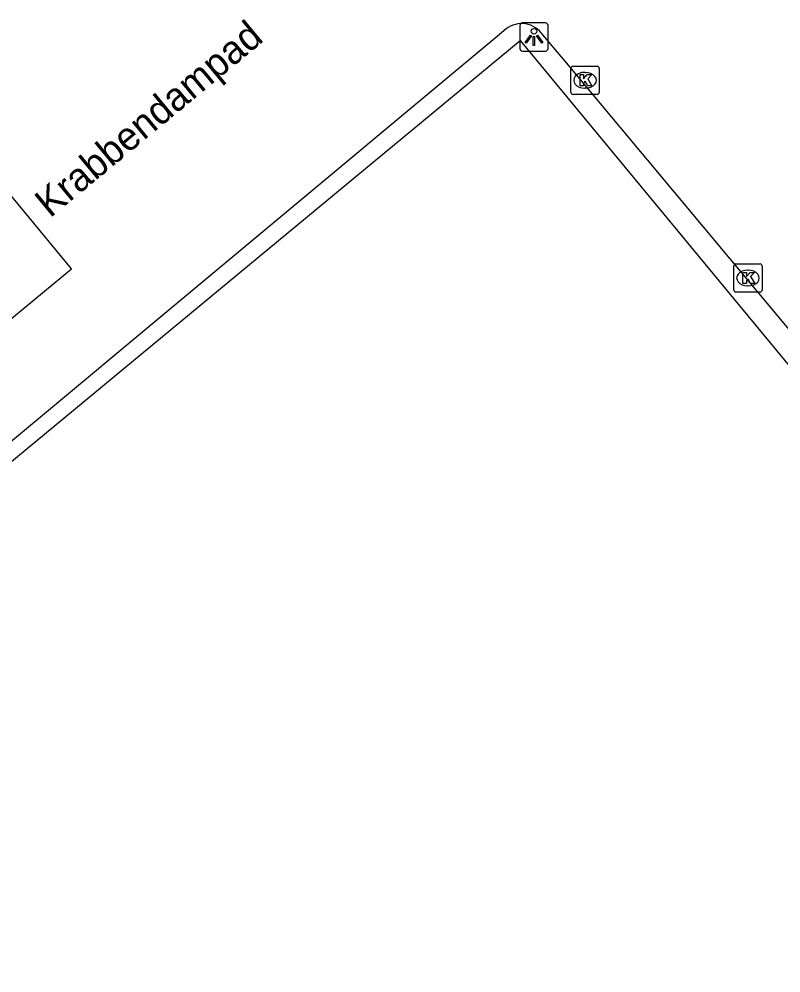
# Model space of a CAD drawing. Extents: x 161087 to 161922, y 382574 to 383873.
# Drawn here: x 161236.47 to 161263.45, y 383205.8 to 383239.57 of the extents above; entities that cross this region are included whole.
import ezdxf

# ---------------------------------------------------------------- set-up
doc = ezdxf.new("R2010")
doc.units = 0
for name, color, linetype in [('IMGEO_Kolk', 7, 'Continuous'), ('IMGEO_Lichtpunt', 7, 'Continuous'), ('IMGEO_Openbare_ruimte_label', 7, 'Continuous'), ('IMGEO_Pand', 7, 'Continuous'), ('IMGEO_Rijbaan_lokaal_open', 7, 'Continuous')]:
    doc.layers.add(name, color=color, linetype=linetype)

msp = doc.modelspace()

# ---------------------------------------------------------------- linework, layer by layer
at = {"layer": 'IMGEO_Kolk'}
for p, q in [((161256.018, 383236.98), (161256.018, 383237.832)), ((161256.093, 383237.906), (161256.945, 383237.906)), ((161256.506, 383237.686), (161256.531, 383237.686)), ((161257.019, 383237.832), (161257.019, 383236.98)), ((161256.529, 383237.126), (161256.504, 383237.126)), ((161256.945, 383236.906), (161256.093, 383236.906)), ((161261.861, 383230.906), (161262.713, 383230.906)), ((161261.786, 383229.98), (161261.786, 383230.832)), ((161262.274, 383230.686), (161262.299, 383230.686)), ((161262.787, 383230.832), (161262.787, 383229.98)), ((161262.713, 383229.906), (161261.861, 383229.906)), ((161262.297, 383230.126), (161262.272, 383230.126))]:
    msp.add_line(p, q, dxfattribs=at)
for points in [[(161256.018, 383236.98), (161256.018, 383237.832)], [(161256.093, 383237.906), (161256.945, 383237.906)], [(161257.019, 383237.832), (161257.019, 383236.98)], [(161256.339, 383237.606), (161256.462, 383237.606), (161256.462, 383237.455), (161256.592, 383237.606), (161256.756, 383237.606), (161256.61, 383237.455), (161256.763, 383237.206), (161256.611, 383237.206), (161256.526, 383237.37), (161256.462, 383237.303), (161256.462, 383237.206), (161256.339, 383237.206), (161256.339, 383237.606)], [(161256.945, 383236.906), (161256.093, 383236.906)], [(161261.861, 383230.906), (161262.713, 383230.906)], [(161261.786, 383229.98), (161261.786, 383230.832)], [(161262.107, 383230.606), (161262.23, 383230.606), (161262.23, 383230.455), (161262.36, 383230.606), (161262.524, 383230.606), (161262.378, 383230.455), (161262.531, 383230.206), (161262.379, 383230.206), (161262.294, 383230.37), (161262.23, 383230.303), (161262.23, 383230.206), (161262.107, 383230.206), (161262.107, 383230.606)], [(161262.787, 383230.832), (161262.787, 383229.98)], [(161262.713, 383229.906), (161261.861, 383229.906)]]:
    msp.add_lwpolyline(points, dxfattribs=at)
for centre, start, end in [((161256.095, 383237.83), 91.552, 178.448), ((161256.095, 383237.83), 91.552, 178.448), ((161256.943, 383237.83), 1.552, 88.448), ((161256.943, 383237.83), 1.552, 88.448), ((161256.095, 383236.982), 181.552, 268.448), ((161256.095, 383236.982), 181.552, 268.448), ((161256.943, 383236.982), 271.552, 358.448), ((161256.943, 383236.982), 271.552, 358.448), ((161261.863, 383230.83), 91.552, 178.448), ((161261.863, 383230.83), 91.552, 178.448), ((161262.711, 383230.83), 1.552, 88.448), ((161262.711, 383230.83), 1.552, 88.448), ((161261.863, 383229.982), 181.552, 268.448), ((161261.863, 383229.982), 181.552, 268.448), ((161262.711, 383229.982), 271.552, 358.448), ((161262.711, 383229.982), 271.552, 358.448)]:
    msp.add_arc(centre, 0.0765, start, end, dxfattribs=at)
for centre, major_axis, ratio, start_param, end_param in [((161256.505, 383237.406), (-0.387, 0.002), 0.722429, 4.712389, 7.853982), ((161256.53, 383237.406), (-0.39, 0.002), 0.717154, 1.570796, 4.712389), ((161262.273, 383230.406), (-0.387, 0.002), 0.722429, 4.712389, 7.853982), ((161262.298, 383230.406), (-0.39, 0.002), 0.717154, 1.570796, 4.712389)]:
    msp.add_ellipse(centre, major_axis=major_axis, ratio=ratio, start_param=start_param, end_param=end_param, dxfattribs=at)
at = {"layer": 'IMGEO_Lichtpunt'}
for p, q in [((161254.209, 383239.344), (161254.209, 383238.537)), ((161254.209, 383239.344), (161254.209, 383238.537)), ((161255.111, 383239.439), (161254.303, 383239.439)), ((161255.111, 383239.439), (161254.303, 383239.439)), ((161255.205, 383238.537), (161255.205, 383239.344)), ((161255.205, 383238.537), (161255.205, 383239.344)), ((161254.303, 383238.443), (161255.111, 383238.443)), ((161254.303, 383238.443), (161255.111, 383238.443))]:
    msp.add_line(p, q, dxfattribs=at)
for points in [[(161254.583, 383239.008), (161254.622, 383238.98), (161254.434, 383238.718), (161254.396, 383238.745), (161254.583, 383239.008)], [(161254.795, 383238.98), (161254.833, 383239.007), (161255.02, 383238.745), (161254.981, 383238.717), (161254.795, 383238.98)], [(161254.685, 383238.96), (161254.732, 383238.96), (161254.732, 383238.638), (161254.685, 383238.638), (161254.685, 383238.96)]]:
    msp.add_lwpolyline(points, dxfattribs=at)
msp.add_circle((161254.708, 383239.142), 0.0994, dxfattribs=at)
for centre, start, end in [((161254.303, 383239.344), 90, 180), ((161254.303, 383239.344), 90, 180), ((161255.111, 383239.344), 0, 90), ((161255.111, 383239.344), 0, 90), ((161254.303, 383238.537), 180, 270), ((161254.303, 383238.537), 180, 270), ((161255.111, 383238.537), 270, 0), ((161255.111, 383238.537), 270, 360)]:
    msp.add_arc(centre, 0.0946, start, end, dxfattribs=at)
at = {"layer": 'IMGEO_Pand'}
for points in [[(161229.145, 383218.076), (161254.221, 383238.815), (161271.644, 383217.75)], [(161235.931, 383228.744), (161238.328, 383230.728), (161234.153, 383235.777), (161231.755, 383233.794)]]:
    msp.add_lwpolyline(points, dxfattribs=at)
at = {"layer": 'IMGEO_Rijbaan_lokaal_open'}
for points in [[(161253.651, 383239.165), (161253.476, 383239.012), (161225.31, 383215.556), (161213.599, 383205.802)], [(161272.41, 383218.205), (161255.801, 383238.095), (161254.96, 383239.082)]]:
    msp.add_lwpolyline(points, dxfattribs=at)
msp.add_arc((161254.268, 383238.525), 0.889, 38.816, 133.9278, dxfattribs=at)

# ---------------------------------------------------------------- texts
at = {"layer": 'IMGEO_Openbare_ruimte_label'}
msp.add_text('Krabbendampad', height=1, rotation=39.6442, dxfattribs=at).set_placement((161237.566, 383232.511))

doc.saveas('drawing.dxf')
